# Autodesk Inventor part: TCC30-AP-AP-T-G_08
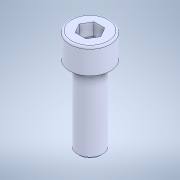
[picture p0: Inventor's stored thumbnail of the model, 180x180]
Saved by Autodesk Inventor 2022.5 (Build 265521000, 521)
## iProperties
Created: 2023-09
Part Number: TCC30-AP-AP-T-G_08
Material: 一般
Document SubType Name: Modeling
Designer: ImaoCorp
Density: 1 g/cm^3
Appearance: 既定
Author: ImaoCorp
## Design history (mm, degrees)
feature "TCC30-AP-AP-T-G_08"
node "ソリッド1"
